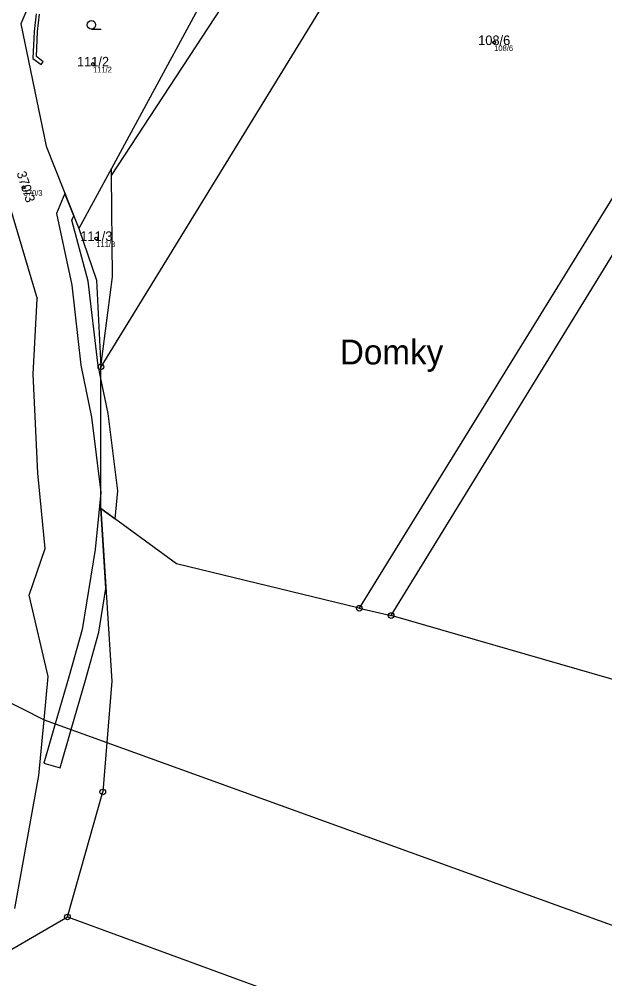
# Model space of a CAD drawing. Extents: x -867966 to -864255, y -1043242 to -1041327.
# Drawn here: x -866296.7 to -866193, y -1042347 to -1042177 of the extents above; entities that cross this region are included whole.
import ezdxf

# ---------------------------------------------------------------- set-up
doc = ezdxf.new("R2010")
doc.units = 0
for name, color, linetype in [('Definiční body', 7, 'Continuous'), ('Hranice parcel', 7, 'Continuous'), ('Parcelní čísla', 7, 'Continuous'), ('Pop  PČ popisy', 7, 'Continuous'), ('Vnitřní kresba', 7, 'Continuous'), ('Věcná břemena k části', 7, 'Continuous'), ('Značky bodu BP', 7, 'Continuous'), ('Značky kultur', 7, 'Continuous')]:
    doc.layers.add(name, color=color, linetype=linetype)

msp = doc.modelspace()

# ---------------------------------------------------------------- linework, layer by layer
at = {"layer": 'Definiční body'}
for centre in [(-866212.55, -1042181.12), (-866283.61, -1042184.91), (-866295.89, -1042206.77), (-866283.02, -1042215.84)]:
    msp.add_circle(centre, 0.25, dxfattribs=at)
at = {"layer": 'Hranice parcel'}
for p, q in [((-866188.35, -1042085.45), (-866282.21, -1042238.58)), ((-866138.24, -1042121.95), (-866236.44, -1042281.35)), ((-866230.8, -1042282.65), (-866134.09, -1042125.03)), ((-866250.24, -1042147.79), (-866280.35, -1042203.45)), ((-866280.34, -1042204.64), (-866247.69, -1042154.86)), ((-866287.19, -1042156.13), (-866296.41, -1042177.81)), ((-866296.41, -1042177.81), (-866291.88, -1042199.46)), ((-866302.55, -1042196.13), (-866293.51, -1042226.51)), ((-866291.88, -1042199.46), (-866286.1, -1042214.08)), ((-866280.35, -1042203.45), (-866286.1, -1042214.08)), ((-866280.34, -1042204.64), (-866280.35, -1042203.45)), ((-866280.16, -1042222.61), (-866280.34, -1042204.64)), ((-866286.1, -1042214.08), (-866282.98, -1042223.23)), ((-866282.98, -1042223.23), (-866282.21, -1042238.58)), ((-866282.21, -1042238.58), (-866280.16, -1042222.61)), ((-866294.18, -1042239.87), (-866293.51, -1042226.51)), ((-866282.2, -1042263.67), (-866282.21, -1042238.58)), ((-866293.4, -1042257.44), (-866294.18, -1042239.87)), ((-866292.11, -1042270.76), (-866293.4, -1042257.44)), ((-866282.2, -1042263.67), (-866280.3, -1042294.28)), ((-866268.8, -1042273.5), (-866282.2, -1042263.67)), ((-866294.91, -1042279.02), (-866292.11, -1042270.76)), ((-866236.44, -1042281.35), (-866268.8, -1042273.5)), ((-866291.55, -1042293.44), (-866294.91, -1042279.02)), ((-866236.44, -1042281.35), (-866230.8, -1042282.65)), ((-866121.99, -1042314.05), (-866230.8, -1042282.65)), ((-866292.28, -1042301.12), (-866291.55, -1042293.44)), ((-866280.3, -1042294.28), (-866281.17, -1042305.14)), ((-866293.22, -1042310.97), (-866292.28, -1042301.12)), ((-866281.17, -1042305.14), (-866281.87, -1042313.91)), ((-866297.45, -1042334.56), (-866293.22, -1042310.97)), ((-866288.13, -1042336.07), (-866281.87, -1042313.91)), ((-866309.8, -1042348.56), (-866288.13, -1042336.07)), ((-866288.13, -1042336.07), (-866248.21, -1042350.72))]:
    msp.add_line(p, q, dxfattribs=at)
at = {"layer": 'Vnitřní kresba'}
for p, q in [((-866329.45, -1042282.38), (-866292.28, -1042301.12)), ((-866292.28, -1042301.12), (-866281.17, -1042305.14)), ((-866281.17, -1042305.14), (-866140.87, -1042355.87))]:
    msp.add_line(p, q, dxfattribs=at)
at = {"layer": 'Věcná břemena k části'}
msp.add_lwpolyline([(-866293.66, -1042175.99), (-866294.04, -1042179.12), (-866294.25, -1042183.9), (-866292.78, -1042184.97), (-866292.42, -1042184.49), (-866293.63, -1042183.6), (-866293.44, -1042179.16), (-866293.06, -1042176.09)], dxfattribs=at)
msp.add_lwpolyline([(-866287.38, -1042224.09), (-866285.76, -1042238.29), (-866283.85, -1042247.49), (-866282.2, -1042260.87), (-866283.22, -1042270.93), (-866285.55, -1042285.11), (-866287.82, -1042293.32), (-866290.29, -1042301.84), (-866292.32, -1042308.83), (-866289.44, -1042309.66), (-866287.47, -1042302.86), (-866284.93, -1042294.12), (-866282.59, -1042285.59), (-866281.32, -1042277.86), (-866282.2, -1042263.67), (-866279.69, -1042265.51), (-866279.22, -1042260.52), (-866280.91, -1042246.87), (-866282.21, -1042240.66), (-866282.78, -1042237.95), (-866284.46, -1042223.4), (-866287.34, -1042212.58), (-866287, -1042211.8), (-866288.57, -1042207.84), (-866290.1, -1042211.41)], close=True, dxfattribs=at)
at = {"layer": 'Značky bodu BP'}
for centre, radius in [((-866282.21, -1042238.58), 0.5), ((-866282.21, -1042238.58), 0.0303), ((-866236.44, -1042281.35), 0.5), ((-866236.44, -1042281.35), 0.0303), ((-866230.8, -1042282.65), 0.5), ((-866230.8, -1042282.65), 0.0303), ((-866281.87, -1042313.91), 0.5), ((-866281.87, -1042313.91), 0.0303), ((-866288.13, -1042336.07), 0.5), ((-866288.13, -1042336.07), 0.0303)]:
    msp.add_circle(centre, radius, dxfattribs=at)
at = {"layer": 'Značky kultur'}
msp.add_line((-866283.9, -1042178.7), (-866282.15, -1042178.7), dxfattribs=at)
msp.add_circle((-866283.9, -1042177.95), 0.75, dxfattribs=at)

# ---------------------------------------------------------------- texts
at = {"layer": 'Definiční body'}
for s, p in [('108/6', (-866212.55, -1042182.61)), ('111/2', (-866283.61, -1042186.4)), ('370/3', (-866295.89, -1042208.26)), ('111/3', (-866283.02, -1042217.33))]:
    msp.add_text(s, height=1, dxfattribs=at).set_placement(p)
at = {"layer": 'Parcelní čísla'}
for s, p in [('108/6', (-866215.39, -1042181.55)), ('111/2', (-866286.45, -1042185.34)), ('111/3', (-866285.86, -1042216.27))]:
    msp.add_text(s, height=1.7, dxfattribs=at).set_placement(p)
msp.add_text('370/3', height=1.7, rotation=288, dxfattribs=at).set_placement((-866297.17, -1042204.2))
at = {"layer": 'Pop  PČ popisy'}
msp.add_text('Domky', height=4.4, dxfattribs=at).set_placement((-866239.88, -1042238.15))

doc.saveas('drawing.dxf')
